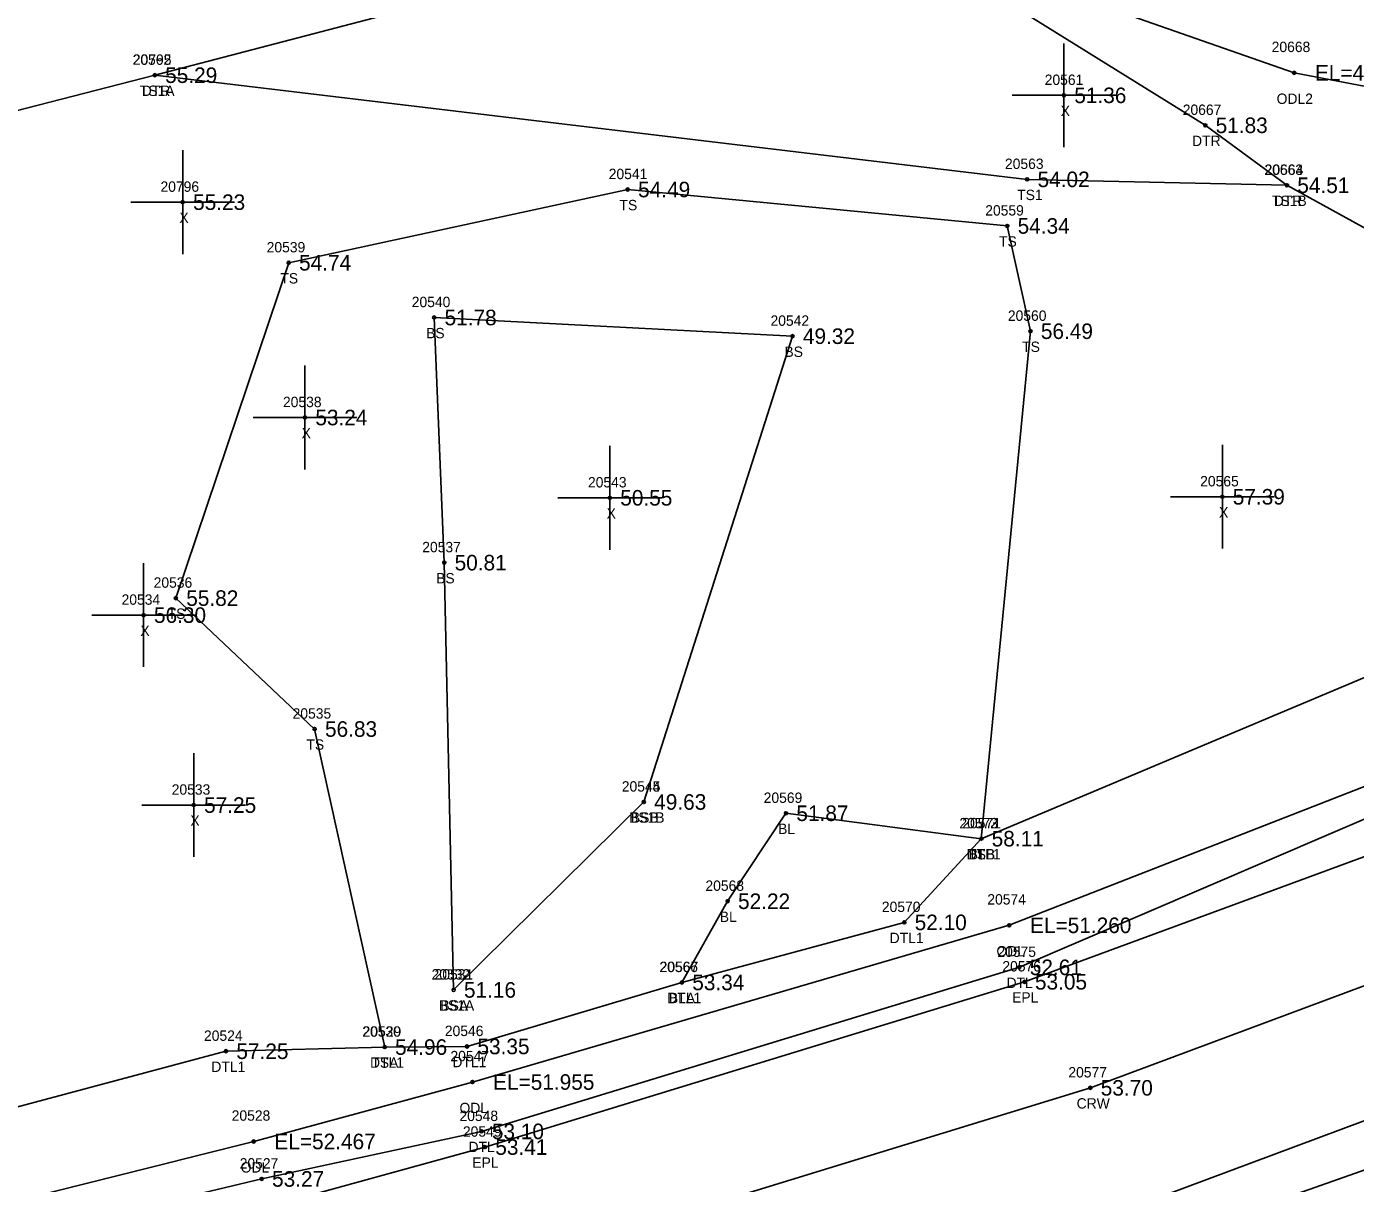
# Model space of a CAD drawing. Extents: x 2420351 to 2422725, y 845330 to 846558.
# Drawn here: x 2421507.3 to 2421635.3, y 845732.5 to 845844 of the extents above; entities that cross this region are included whole.
import ezdxf

# ---------------------------------------------------------------- set-up
doc = ezdxf.new("R2010")
doc.units = 0
for name, color, linetype in [('RD_DTM_BkLn1', 7, 'Continuous'), ('RD_DTM_BkLn2', 7, 'Continuous'), ('RD_DTM_BkLn_txCode', 7, 'Continuous'), ('RD_EX_H2O', 7, 'Continuous'), ('RD_EX_H2O_txCode', 7, 'Continuous'), ('RD_EX_Misc', 7, 'Continuous'), ('RD_EX_Misc_txCode', 7, 'Continuous'), ('RD_EX_Road', 7, 'Continuous'), ('RD_EX_Road_txCode', 7, 'Continuous'), ('RD_EX_TX_H2O_ELEV', 7, 'Continuous'), ('RD_EX_TX_Misc_ELEV', 7, 'Continuous'), ('RD_EX_TX_Road_ELEV', 7, 'Continuous'), ('RD_HC_Survey_ELEV', 7, 'Continuous'), ('RD_HC_Survey_txCode', 7, 'Continuous'), ('RD_SMD_Locator', 7, 'Continuous')]:
    doc.layers.add(name, color=color, linetype=linetype)

msp = doc.modelspace()

# ---------------------------------------------------------------- linework, layer by layer
at = {"layer": 'RD_DTM_BkLn1'}
for points in [[(2420378.71, 845690.53), (2420439.5, 845704.09), (2420489.95, 845712.49), (2420551.89, 845719.42), (2420551.95, 845719.57), (2420607.12, 845722.67), (2420682.92, 845723.04), (2420749.65, 845719.68), (2420796.31, 845715.7), (2420900.74, 845705.33), (2421018.16, 845694.11), (2421114.61, 845684.8), (2421175.74, 845680.1), (2421234.97, 845678.35), (2421292.42, 845679.46), (2421350.56, 845683.65), (2421414.53, 845692.12), (2421472.54, 845703.63), (2421533.08, 845718.31), (2421555.4, 845725.02), (2421609.81, 845741.71), (2421666.58, 845762.88), (2421744.67, 845798.22)], [(2421570.45, 845751.87), (2421574.86, 845759.7), (2421580.48, 845768.18), (2421599.3, 845765.73)]]:
    msp.add_lwpolyline(points, dxfattribs=at)
at = {"layer": 'RD_DTM_BkLn2'}
msp.add_line((2421548.45, 845751.15), (2421566.78, 845769.27), dxfattribs=at)
for points in [[(2421519.66, 845839.33), (2421603.72, 845829.29), (2421628.75, 845828.72)], [(2421541.81, 845745.64), (2421535.06, 845776.3), (2421521.69, 845788.92), (2421532.56, 845821.25), (2421565.23, 845828.31), (2421601.8, 845824.8), (2421604.04, 845814.65), (2421599.3, 845765.73)], [(2421548.45, 845751.15), (2421547.55, 845792.34), (2421546.58, 845815.97), (2421581.11, 845814.17), (2421566.78, 845769.27)]]:
    msp.add_lwpolyline(points, dxfattribs=at)
at = {"layer": 'RD_EX_H2O'}
for points in [[(2420975.55, 846190.58), (2420976.37, 846105.11), (2420974.31, 845997.82), (2420976.03, 845896.74), (2420974.59, 845794.18), (2420975.37, 845743.63), (2420984.12, 845720.99), (2420999.91, 845711.18), (2421116.7, 845699.77), (2421177.35, 845696.01), (2421236.57, 845694.11), (2421292.07, 845694.75), (2421349.67, 845700.43), (2421411.57, 845706.56), (2421470.63, 845718.76), (2421529.96, 845732.93), (2421551.14, 845737.51), (2421602.97, 845753.33), (2421656.85, 845776.48), (2421724.45, 845805.15), (2421739.21, 845812.56)], [(2420980.17, 846190.47), (2420980.93, 846104.85), (2420980.02, 845997.99), (2420979.17, 845896.92), (2420978.72, 845794), (2420978.72, 845743.89), (2420987.58, 845724.3), (2421000.53, 845717.13), (2421117.24, 845704.33), (2421178.3, 845699.94), (2421237.1, 845697.97), (2421292.37, 845698.66), (2421349.43, 845702.84), (2421410.88, 845710.25), (2421469.94, 845721.7), (2421529.19, 845736.54), (2421550.26, 845742.27), (2421602, 845757.38), (2421655.89, 845778.44), (2421721.41, 845810.89), (2421742.22, 845823.45)], [(2421712.23, 845851.64), (2421696.17, 845853.46), (2421673.72, 845844.59), (2421672.85, 845833.86), (2421657.19, 845821.05), (2421639.52, 845822.79), (2421628.75, 845828.72), (2421620.88, 845834.5), (2421598.01, 845848.76), (2421559.66, 845849.82), (2421519.66, 845839.33), (2421490.26, 845831.77), (2421489.16, 845834.56), (2421488.34, 845838.76), (2421481.47, 845840.1), (2421478.52, 845840.67), (2421462.88, 845836.78), (2421401.68, 845880.53), (2421390.37, 845914.71), (2421413.41, 845969.29), (2421455.53, 845995.93), (2421500.71, 846029.14), (2421506.65, 846045.11), (2421509.82, 846047.43)], [(2421708.19, 845857.7), (2421694.83, 845854.97), (2421672.77, 845845.6), (2421652.18, 845835.21), (2421629.45, 845839.56), (2421596.22, 845851.19), (2421557.52, 845853.76), (2421517.9, 845849.31), (2421470, 845855.59), (2421412.32, 845890.59), (2421407.69, 845919.26), (2421422.64, 845967.89), (2421458.88, 845993.64), (2421465.81, 845995.46), (2421507.94, 846023.27)], [(2421348.44, 845711.4), (2421408.11, 845718.43), (2421468.58, 845729.77), (2421526.52, 845745.24), (2421541.81, 845745.64), (2421549.75, 845745.7), (2421570.45, 845751.87), (2421591.88, 845757.66), (2421599.3, 845765.73), (2421650.04, 845787.07), (2421668.02, 845786.79), (2421719.15, 845813.59), (2421740.13, 845828.42)], [(2421462.85, 845683.51), (2421560.11, 845709.79), (2421615.97, 845726.65), (2421668.49, 845745.18), (2421738.54, 845774.52), (2421754.61, 845783.24)]]:
    msp.add_lwpolyline(points, dxfattribs=at)
at = {"layer": 'RD_EX_Misc'}
for p, q in [((2421607.26, 845832.39), (2421607.26, 845842.39)), ((2421602.26, 845837.39), (2421612.26, 845837.39)), ((2421522.35, 845822.09), (2421522.35, 845832.09)), ((2421517.35, 845827.09), (2421527.35, 845827.09)), ((2421534.13, 845801.33), (2421534.13, 845811.33)), ((2421529.13, 845806.33), (2421539.13, 845806.33)), ((2421563.51, 845793.59), (2421563.51, 845803.59)), ((2421622.53, 845793.69), (2421622.53, 845803.69)), ((2421558.51, 845798.59), (2421568.51, 845798.59)), ((2421617.53, 845798.69), (2421627.53, 845798.69)), ((2421518.58, 845782.28), (2421518.58, 845792.28)), ((2421513.58, 845787.28), (2421523.58, 845787.28)), ((2421523.41, 845763.97), (2421523.41, 845773.97)), ((2421518.41, 845768.97), (2421528.41, 845768.97))]:
    msp.add_line(p, q, dxfattribs=at)
at = {"layer": 'RD_EX_Road'}
for points in [[(2420388.28, 845680.39), (2420441.29, 845692.04), (2420492.62, 845700.7), (2420553.92, 845707.41), (2420607.69, 845710.85), (2420682.38, 845711.26), (2420749.44, 845707.27), (2420795.12, 845703.44), (2420900.28, 845693.42), (2421017.17, 845682.19), (2421113.9, 845672.97), (2421174.87, 845668.16), (2421234.59, 845666.13), (2421293, 845667.25), (2421351.24, 845671.5), (2421419.82, 845681.17), (2421463.19, 845688.63), (2421558.82, 845713.18), (2421614.57, 845730.45), (2421670.73, 845751.42), (2421735.61, 845780.5), (2421750.75, 845787.87), (2421744.67, 845798.22), (2421739.21, 845808.11)], [(2421350.22, 845695.49), (2421412.35, 845704.28), (2421471.12, 845715.7), (2421530.23, 845730.14), (2421551.47, 845736), (2421603.47, 845751.93), (2421659.09, 845772.43), (2421726.04, 845802.13), (2421739.21, 845808.11)]]:
    msp.add_lwpolyline(points, dxfattribs=at)
at = {"layer": 'RD_SMD_Locator'}
for centre in [(2421519.66, 845839.33), (2421519.66, 845839.33), (2421629.45, 845839.56), (2421607.26, 845837.39), (2421620.88, 845834.5), (2421603.72, 845829.29), (2421565.23, 845828.31), (2421628.75, 845828.72), (2421628.75, 845828.72), (2421522.35, 845827.09), (2421601.8, 845824.8), (2421532.56, 845821.25), (2421546.58, 845815.97), (2421581.11, 845814.17), (2421604.04, 845814.65), (2421534.13, 845806.33), (2421563.51, 845798.59), (2421622.53, 845798.69), (2421547.55, 845792.34), (2421521.69, 845788.92), (2421518.58, 845787.28), (2421535.06, 845776.3), (2421523.41, 845768.97), (2421566.78, 845769.27), (2421566.78, 845769.27), (2421580.48, 845768.18), (2421599.3, 845765.73), (2421599.3, 845765.73), (2421599.3, 845765.73), (2421574.86, 845759.7), (2421591.88, 845757.66), (2421602, 845757.38), (2421602.97, 845753.33), (2421548.45, 845751.15), (2421548.45, 845751.15), (2421570.45, 845751.87), (2421570.45, 845751.87), (2421603.47, 845751.93), (2421526.52, 845745.24), (2421541.81, 845745.64), (2421541.81, 845745.64), (2421549.75, 845745.7), (2421550.26, 845742.27), (2421609.81, 845741.71), (2421551.14, 845737.51), (2421529.19, 845736.54), (2421551.47, 845736), (2421529.96, 845732.93)]:
    msp.add_circle(centre, 0.15, dxfattribs=at)

# ---------------------------------------------------------------- texts
at = {"layer": 'RD_DTM_BkLn_txCode'}
for s, p in [('20562', (2421517.52, 845840.33)), ('TS1A', (2421518.22, 845837.33)), ('20563', (2421601.58, 845830.29)), ('20564', (2421626.61, 845829.72)), ('20541', (2421563.4, 845829.31)), ('TS1', (2421602.76, 845827.29)), ('TS', (2421564.44, 845826.31)), ('20559', (2421599.68, 845825.8)), ('TS1B', (2421627.31, 845826.72)), ('20539', (2421530.44, 845822.25)), ('TS', (2421601.01, 845822.8)), ('TS', (2421531.76, 845819.25)), ('20540', (2421544.42, 845816.97)), ('20560', (2421601.86, 845815.65)), ('20542', (2421578.99, 845815.17)), ('BS', (2421545.8, 845813.97)), ('BS', (2421580.33, 845812.17)), ('TS', (2421603.24, 845812.65)), ('20537', (2421545.43, 845793.34)), ('20536', (2421519.55, 845789.92)), ('BS', (2421546.77, 845790.34)), ('TS', (2421520.9, 845786.92)), ('20535', (2421532.94, 845777.3)), ('TS', (2421534.27, 845774.3)), ('20544', (2421564.66, 845770.27)), ('20545', (2421564.66, 845770.27)), ('20569', (2421578.33, 845769.18)), ('BS1B', (2421565.36, 845767.27)), ('BSB', (2421565.53, 845767.27)), ('20572', (2421597.19, 845766.73)), ('20573', (2421597.19, 845766.73)), ('BL', (2421579.72, 845766.18)), ('TSB', (2421598.04, 845763.73)), ('BLB', (2421598.08, 845763.73)), ('20568', (2421572.72, 845760.7)), ('BL', (2421574.1, 845757.7)), ('20567', (2421568.31, 845752.87)), ('20532', (2421546.33, 845752.15)), ('20531', (2421546.62, 845752.15)), ('BS1A', (2421547.02, 845749.15)), ('BSA', (2421547.18, 845749.15)), ('BLA', (2421569.2, 845749.87)), ('20530', (2421539.65, 845746.64)), ('TSA', (2421540.53, 845743.64))]:
    msp.add_text(s, height=1, dxfattribs=at).set_placement(p)
at = {"layer": 'RD_EX_H2O_txCode'}
for s, p in [('20668', (2421627.28, 845841.56)), ('20795', (2421517.55, 845840.33)), ('DTR', (2421518.4, 845837.33)), ('ODL2', (2421627.76, 845836.56)), ('20667', (2421618.71, 845835.5)), ('DTR', (2421619.61, 845832.5)), ('20663', (2421626.58, 845829.72)), ('DTR', (2421627.48, 845826.72)), ('20571', (2421597.47, 845766.73)), ('DTL1', (2421597.89, 845763.73)), ('20574', (2421599.88, 845759.38)), ('20570', (2421589.72, 845758.66)), ('DTL1', (2421590.47, 845755.66)), ('ODL', (2421600.76, 845754.38)), ('20575', (2421600.85, 845754.33)), ('20566', (2421568.28, 845752.87)), ('DTL', (2421601.73, 845751.33)), ('DTL1', (2421569.04, 845749.87)), ('20524', (2421524.4, 845746.24)), ('20529', (2421539.69, 845746.64)), ('20546', (2421547.61, 845746.7)), ('DTL1', (2421540.4, 845743.64)), ('20547', (2421548.15, 845744.27)), ('DTL1', (2421548.34, 845743.7)), ('DTL1', (2421525.11, 845743.24)), ('20528', (2421527.07, 845738.54)), ('ODL', (2421549.02, 845739.27)), ('20548', (2421549.02, 845738.51)), ('DTL', (2421549.89, 845735.51)), ('20527', (2421527.84, 845733.93)), ('ODL', (2421527.94, 845733.54))]:
    msp.add_text(s, height=1, dxfattribs=at).set_placement(p)
at = {"layer": 'RD_EX_Misc_txCode'}
for s, p in [('20561', (2421605.41, 845838.39)), ('X', (2421606.95, 845835.39)), ('20796', (2421520.21, 845828.09)), ('X', (2421522.03, 845825.09)), ('20538', (2421532.01, 845807.33)), ('X', (2421533.81, 845804.33)), ('20543', (2421561.4, 845799.59)), ('20565', (2421620.39, 845799.69)), ('X', (2421563.2, 845796.59)), ('X', (2421622.21, 845796.69)), ('20534', (2421516.46, 845788.28)), ('X', (2421518.27, 845785.28)), ('20533', (2421521.29, 845769.97)), ('X', (2421523.09, 845766.97))]:
    msp.add_text(s, height=1, dxfattribs=at).set_placement(p)
at = {"layer": 'RD_EX_Road_txCode'}
for s, p in [('20576', (2421601.33, 845752.93)), ('EPL', (2421602.27, 845749.93)), ('20549', (2421549.35, 845737)), ('EPL', (2421550.26, 845734))]:
    msp.add_text(s, height=1, dxfattribs=at).set_placement(p)
at = {"layer": 'RD_EX_TX_H2O_ELEV'}
for s, p in [('55.29', (2421520.66, 845838.58)), ('EL=43.804', (2421631.45, 845838.81)), ('51.83', (2421621.88, 845833.75)), ('54.51', (2421629.75, 845827.97)), ('58.11', (2421600.3, 845764.98)), ('52.10', (2421592.88, 845756.91)), ('EL=51.260', (2421604, 845756.63)), ('52.61', (2421603.97, 845752.58)), ('53.34', (2421571.45, 845751.12)), ('57.25', (2421527.52, 845744.49)), ('54.96', (2421542.81, 845744.89)), ('53.35', (2421550.75, 845744.95)), ('EL=51.955', (2421552.26, 845741.52)), ('53.10', (2421552.14, 845736.76)), ('EL=52.467', (2421531.19, 845735.79)), ('53.27', (2421530.96, 845732.18))]:
    msp.add_text(s, height=1.5, dxfattribs=at).set_placement(p)
at = {"layer": 'RD_EX_TX_Misc_ELEV'}
for s, p in [('55.29', (2421520.66, 845838.58)), ('51.36', (2421608.26, 845836.64)), ('54.02', (2421604.72, 845828.54)), ('54.51', (2421629.75, 845827.97)), ('55.23', (2421523.35, 845826.34)), ('54.49', (2421566.23, 845827.56)), ('54.34', (2421602.8, 845824.05)), ('54.74', (2421533.56, 845820.5)), ('51.78', (2421547.58, 845815.22)), ('56.49', (2421605.04, 845813.9)), ('49.32', (2421582.11, 845813.42)), ('53.24', (2421535.13, 845805.58)), ('50.55', (2421564.51, 845797.84)), ('57.39', (2421623.53, 845797.94)), ('50.81', (2421548.55, 845791.59)), ('55.82', (2421522.69, 845788.17)), ('56.30', (2421519.58, 845786.53)), ('56.83', (2421536.06, 845775.55)), ('57.25', (2421524.41, 845768.22)), ('49.63', (2421567.78, 845768.52)), ('49.63', (2421567.78, 845768.52)), ('51.87', (2421581.48, 845767.43)), ('58.11', (2421600.3, 845764.98)), ('58.11', (2421600.3, 845764.98)), ('52.22', (2421575.86, 845758.95)), ('53.34', (2421571.45, 845751.12)), ('51.16', (2421549.45, 845750.4)), ('51.16', (2421549.45, 845750.4)), ('54.96', (2421542.81, 845744.89))]:
    msp.add_text(s, height=1.5, dxfattribs=at).set_placement(p)
at = {"layer": 'RD_EX_TX_Road_ELEV'}
for s, p in [('53.05', (2421604.47, 845751.18)), ('53.41', (2421552.47, 845735.25))]:
    msp.add_text(s, height=1.5, dxfattribs=at).set_placement(p)
at = {"layer": 'RD_HC_Survey_ELEV'}
msp.add_text('53.70', height=1.5, dxfattribs=at).set_placement((2421610.81, 845740.96))
at = {"layer": 'RD_HC_Survey_txCode'}
for s, p in [('20577', (2421607.69, 845742.71)), ('CRW', (2421608.49, 845739.71))]:
    msp.add_text(s, height=1, dxfattribs=at).set_placement(p)

doc.saveas('drawing.dxf')
